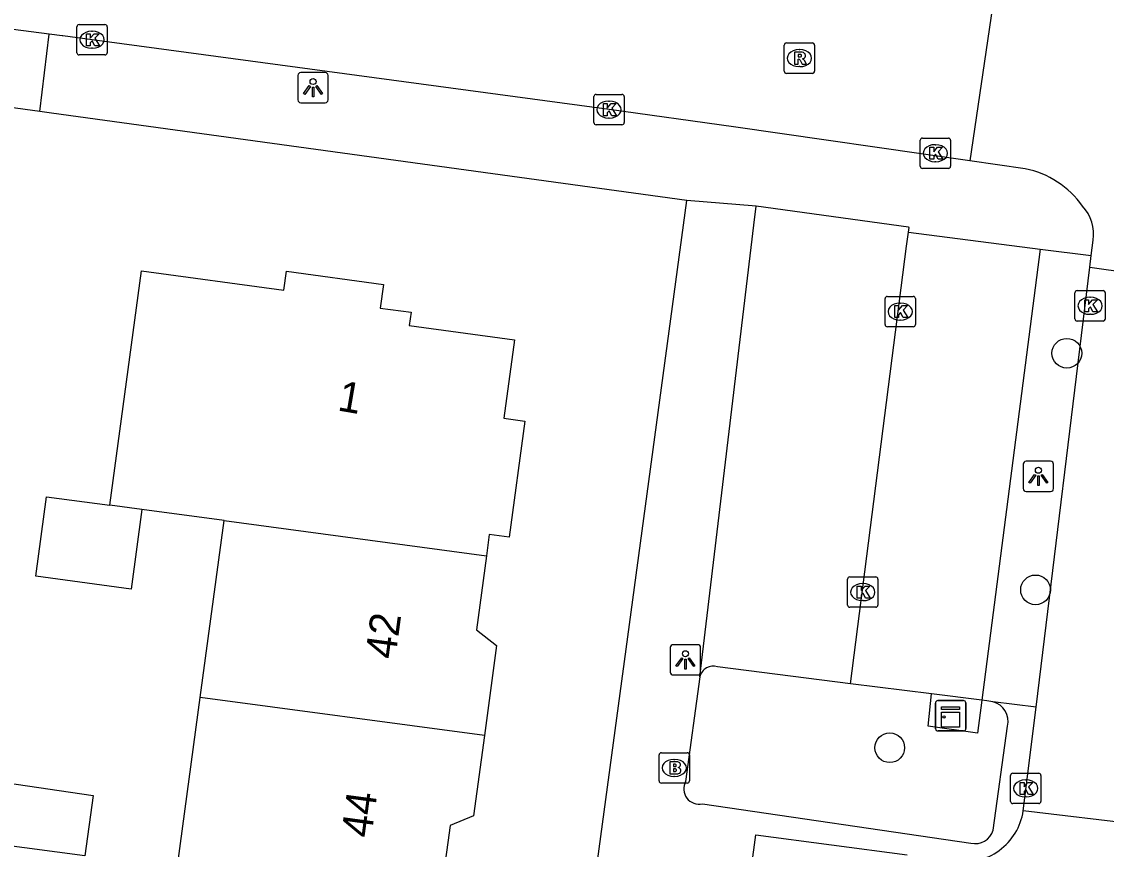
# Model space of a CAD drawing. Extents: x 161258 to 161838, y 380836 to 381727.
# Drawn here: x 161703.9 to 161739.61, y 381549.82 to 381577.07 of the extents above; entities that cross this region are included whole.
import ezdxf

# ---------------------------------------------------------------- set-up
doc = ezdxf.new("R2010")
doc.units = 0
for name, color, linetype in [('IMGEO_Boom', 7, 'Continuous'), ('IMGEO_Brandkraan', 7, 'Continuous'), ('IMGEO_Kast', 7, 'Continuous'), ('IMGEO_Kolk', 7, 'Continuous'), ('IMGEO_Lichtpunt', 7, 'Continuous'), ('IMGEO_Pand', 7, 'Continuous'), ('IMGEO_Pand_nummerreeks', 7, 'Continuous'), ('IMGEO_Parkeervlak_open', 7, 'Continuous'), ('IMGEO_Rijbaan_lokaal_open', 7, 'Continuous'), ('IMGEO_Rioolput', 7, 'Continuous'), ('IMGEO_Voetpad_open', 7, 'Continuous')]:
    doc.layers.add(name, color=color, linetype=linetype)

msp = doc.modelspace()

# ---------------------------------------------------------------- linework, layer by layer
at = {"layer": 'IMGEO_Boom'}
for centre in [(161738.307, 381566.149), (161737.276, 381558.359), (161732.475, 381553.163)]:
    msp.add_circle(centre, 0.489, dxfattribs=at)
at = {"layer": 'IMGEO_Brandkraan'}
for p, q in [((161724.958, 381552.998), (161725.81, 381552.998)), ((161724.883, 381552.072), (161724.883, 381552.924)), ((161725.371, 381552.778), (161725.396, 381552.778)), ((161725.884, 381552.924), (161725.884, 381552.072)), ((161725.81, 381551.998), (161724.958, 381551.998)), ((161725.394, 381552.218), (161725.369, 381552.218))]:
    msp.add_line(p, q, dxfattribs=at)
for points in [[(161724.958, 381552.998), (161725.81, 381552.998)], [(161724.883, 381552.072), (161724.883, 381552.924)], [(161725.231, 381552.698), (161725.231, 381552.298), (161725.444, 381552.298)], [(161725.462, 381552.698), (161725.231, 381552.698)], [(161725.41, 381552.617), (161725.356, 381552.617), (161725.356, 381552.541)], [(161725.884, 381552.924), (161725.884, 381552.072)], [(161725.356, 381552.541), (161725.409, 381552.541)], [(161725.418, 381552.465), (161725.356, 381552.465), (161725.356, 381552.384)], [(161725.356, 381552.384), (161725.418, 381552.384)], [(161725.81, 381551.998), (161724.958, 381551.998)]]:
    msp.add_lwpolyline(points, dxfattribs=at)
for centre, radius, start, end in [((161724.96, 381552.922), 0.0765, 91.552, 178.448), ((161724.96, 381552.922), 0.0765, 91.552, 178.448), ((161725.808, 381552.922), 0.0765, 1.552, 88.448), ((161725.808, 381552.922), 0.0765, 1.552, 88.448), ((161725.411, 381552.579), 0.0379, 267.8285, 90.9355), ((161725.466, 381552.553), 0.145, 59.4692, 91.5367), ((161725.491, 381552.6), 0.0922, 285.5137, 58.1501), ((161725.419, 381552.424), 0.0404, 269.8759, 90.5077), ((161725.45, 381552.549), 0.251, 268.6676, 293.5347), ((161725.496, 381552.408), 0.105, 301.3115, 78.989), ((161724.96, 381552.074), 0.0765, 181.552, 268.448), ((161724.96, 381552.074), 0.0765, 181.552, 268.448), ((161725.808, 381552.074), 0.0765, 271.552, 358.448), ((161725.808, 381552.074), 0.0765, 271.552, 358.448)]:
    msp.add_arc(centre, radius, start, end, dxfattribs=at)
for centre, major_axis, ratio, start_param, end_param in [((161725.37, 381552.498), (-0.387, 0.002), 0.722429, 4.712389, 7.853982), ((161725.395, 381552.498), (-0.39, 0.002), 0.717154, 1.570796, 4.712389)]:
    msp.add_ellipse(centre, major_axis=major_axis, ratio=ratio, start_param=start_param, end_param=end_param, dxfattribs=at)
at = {"layer": 'IMGEO_Kast'}
for p, q in [((161733.983, 381553.788), (161733.983, 381554.629)), ((161733.983, 381554.629), (161733.983, 381553.788)), ((161734.058, 381554.713), (161734.899, 381554.713)), ((161734.899, 381554.713), (161734.058, 381554.713)), ((161734.983, 381554.638), (161734.983, 381553.797)), ((161734.983, 381553.797), (161734.983, 381554.638)), ((161734.908, 381553.713), (161734.067, 381553.713)), ((161734.067, 381553.713), (161734.908, 381553.713))]:
    msp.add_line(p, q, dxfattribs=at)
for points in [[(161734.178, 381554.503), (161734.778, 381554.503), (161734.778, 381554.418), (161734.178, 381554.418), (161734.178, 381554.503)], [(161734.178, 381554.328), (161734.778, 381554.328), (161734.778, 381553.839), (161734.178, 381553.839), (161734.178, 381554.328)]]:
    msp.add_lwpolyline(points, dxfattribs=at)
msp.add_circle((161734.262, 381554.177), 0.0377, dxfattribs=at)
for centre, start, end in [((161734.061, 381554.635), 92.4484, 184.2845), ((161734.061, 381554.635), 92.4484, 184.2845), ((161734.905, 381554.635), 2.4484, 94.2845), ((161734.905, 381554.635), 2.4484, 94.2845), ((161734.061, 381553.791), 182.4484, 274.2845), ((161734.061, 381553.791), 182.4484, 274.2845), ((161734.905, 381553.791), 272.4484, 4.2845), ((161734.905, 381553.791), 272.4484, 4.2845)]:
    msp.add_arc(centre, 0.0779, start, end, dxfattribs=at)
at = {"layer": 'IMGEO_Kolk'}
for p, q in [((161705.713, 381576.047), (161705.713, 381576.899)), ((161705.788, 381576.973), (161706.64, 381576.973)), ((161706.714, 381576.899), (161706.714, 381576.047)), ((161706.201, 381576.753), (161706.226, 381576.753)), ((161706.224, 381576.193), (161706.199, 381576.193)), ((161706.64, 381575.973), (161705.788, 381575.973)), ((161722.733, 381573.747), (161722.733, 381574.599)), ((161722.808, 381574.673), (161723.66, 381574.673)), ((161723.221, 381574.453), (161723.246, 381574.453)), ((161723.734, 381574.599), (161723.734, 381573.747)), ((161723.66, 381573.673), (161722.808, 381573.673)), ((161723.244, 381573.893), (161723.219, 381573.893)), ((161733.48, 381572.311), (161733.48, 381573.163)), ((161733.555, 381573.237), (161734.407, 381573.237)), ((161733.968, 381573.017), (161733.993, 381573.017)), ((161734.481, 381573.163), (161734.481, 381572.311)), ((161734.407, 381572.237), (161733.555, 381572.237)), ((161733.991, 381572.457), (161733.966, 381572.457)), ((161732.322, 381567.097), (161732.322, 381567.949)), ((161732.397, 381568.023), (161733.249, 381568.023)), ((161733.323, 381567.949), (161733.323, 381567.097)), ((161738.573, 381567.286), (161738.573, 381568.138)), ((161738.648, 381568.212), (161739.5, 381568.212)), ((161739.061, 381567.992), (161739.086, 381567.992)), ((161739.574, 381568.138), (161739.574, 381567.286)), ((161732.81, 381567.803), (161732.835, 381567.803)), ((161732.833, 381567.243), (161732.808, 381567.243)), ((161739.084, 381567.432), (161739.059, 381567.432)), ((161733.249, 381567.023), (161732.397, 381567.023)), ((161739.5, 381567.212), (161738.648, 381567.212)), ((161731.088, 381557.859), (161731.088, 381558.711)), ((161731.163, 381558.785), (161732.015, 381558.785)), ((161732.089, 381558.711), (161732.089, 381557.859)), ((161731.576, 381558.565), (161731.601, 381558.565)), ((161731.599, 381558.005), (161731.574, 381558.005)), ((161732.015, 381557.785), (161731.163, 381557.785)), ((161736.453, 381551.396), (161736.453, 381552.248)), ((161736.528, 381552.322), (161737.38, 381552.322)), ((161737.454, 381552.248), (161737.454, 381551.396)), ((161736.941, 381552.102), (161736.966, 381552.102)), ((161736.964, 381551.542), (161736.939, 381551.542)), ((161737.38, 381551.322), (161736.528, 381551.322))]:
    msp.add_line(p, q, dxfattribs=at)
for points in [[(161705.713, 381576.047), (161705.713, 381576.899)], [(161705.788, 381576.973), (161706.64, 381576.973)], [(161706.714, 381576.899), (161706.714, 381576.047)], [(161706.034, 381576.673), (161706.157, 381576.673), (161706.157, 381576.522), (161706.287, 381576.673), (161706.451, 381576.673), (161706.305, 381576.522), (161706.458, 381576.273), (161706.306, 381576.273), (161706.221, 381576.437), (161706.157, 381576.37), (161706.157, 381576.273), (161706.034, 381576.273), (161706.034, 381576.673)], [(161706.64, 381575.973), (161705.788, 381575.973)], [(161722.733, 381573.747), (161722.733, 381574.599)], [(161722.808, 381574.673), (161723.66, 381574.673)], [(161723.054, 381574.373), (161723.177, 381574.373), (161723.177, 381574.222), (161723.307, 381574.373), (161723.471, 381574.373), (161723.325, 381574.222), (161723.478, 381573.973), (161723.326, 381573.973), (161723.241, 381574.137), (161723.177, 381574.07), (161723.177, 381573.973), (161723.054, 381573.973), (161723.054, 381574.373)], [(161723.734, 381574.599), (161723.734, 381573.747)], [(161723.66, 381573.673), (161722.808, 381573.673)], [(161733.48, 381572.311), (161733.48, 381573.163)], [(161733.555, 381573.237), (161734.407, 381573.237)], [(161733.801, 381572.937), (161733.924, 381572.937), (161733.924, 381572.786), (161734.054, 381572.937), (161734.218, 381572.937), (161734.072, 381572.786), (161734.225, 381572.537), (161734.073, 381572.537), (161733.988, 381572.701), (161733.924, 381572.634), (161733.924, 381572.537), (161733.801, 381572.537), (161733.801, 381572.937)], [(161734.481, 381573.163), (161734.481, 381572.311)], [(161734.407, 381572.237), (161733.555, 381572.237)], [(161732.322, 381567.097), (161732.322, 381567.949)], [(161732.397, 381568.023), (161733.249, 381568.023)], [(161733.323, 381567.949), (161733.323, 381567.097)], [(161738.573, 381567.286), (161738.573, 381568.138)], [(161738.648, 381568.212), (161739.5, 381568.212)], [(161739.574, 381568.138), (161739.574, 381567.286)], [(161732.643, 381567.723), (161732.766, 381567.723), (161732.766, 381567.572), (161732.896, 381567.723), (161733.06, 381567.723), (161732.914, 381567.572), (161733.067, 381567.323), (161732.915, 381567.323), (161732.83, 381567.487), (161732.766, 381567.42), (161732.766, 381567.323), (161732.643, 381567.323), (161732.643, 381567.723)], [(161738.894, 381567.912), (161739.017, 381567.912), (161739.017, 381567.761), (161739.147, 381567.912), (161739.311, 381567.912), (161739.165, 381567.761), (161739.318, 381567.512), (161739.166, 381567.512), (161739.081, 381567.676), (161739.017, 381567.609), (161739.017, 381567.512), (161738.894, 381567.512), (161738.894, 381567.912)], [(161733.249, 381567.023), (161732.397, 381567.023)], [(161739.5, 381567.212), (161738.648, 381567.212)], [(161731.088, 381557.859), (161731.088, 381558.711)], [(161731.163, 381558.785), (161732.015, 381558.785)], [(161732.089, 381558.711), (161732.089, 381557.859)], [(161731.409, 381558.485), (161731.532, 381558.485), (161731.532, 381558.334), (161731.662, 381558.485), (161731.826, 381558.485), (161731.68, 381558.334), (161731.833, 381558.085), (161731.681, 381558.085), (161731.596, 381558.249), (161731.532, 381558.182), (161731.532, 381558.085), (161731.409, 381558.085), (161731.409, 381558.485)], [(161732.015, 381557.785), (161731.163, 381557.785)], [(161736.453, 381551.396), (161736.453, 381552.248)], [(161736.528, 381552.322), (161737.38, 381552.322)], [(161737.454, 381552.248), (161737.454, 381551.396)], [(161736.774, 381552.022), (161736.897, 381552.022), (161736.897, 381551.871), (161737.027, 381552.022), (161737.191, 381552.022), (161737.045, 381551.871), (161737.198, 381551.622), (161737.046, 381551.622), (161736.961, 381551.786), (161736.897, 381551.719), (161736.897, 381551.622), (161736.774, 381551.622), (161736.774, 381552.022)], [(161737.38, 381551.322), (161736.528, 381551.322)]]:
    msp.add_lwpolyline(points, dxfattribs=at)
for centre, start, end in [((161705.79, 381576.897), 91.552, 178.448), ((161705.79, 381576.897), 91.552, 178.448), ((161706.638, 381576.897), 1.552, 88.448), ((161706.638, 381576.897), 1.552, 88.448), ((161705.79, 381576.049), 181.552, 268.448), ((161705.79, 381576.049), 181.552, 268.448), ((161706.638, 381576.049), 271.552, 358.448), ((161706.638, 381576.049), 271.552, 358.448), ((161722.81, 381574.597), 91.552, 178.448), ((161722.81, 381574.597), 91.552, 178.448), ((161723.658, 381574.597), 1.552, 88.448), ((161723.658, 381574.597), 1.552, 88.448), ((161722.81, 381573.749), 181.552, 268.448), ((161722.81, 381573.749), 181.552, 268.448), ((161723.658, 381573.749), 271.552, 358.448), ((161723.658, 381573.749), 271.552, 358.448), ((161733.557, 381573.161), 91.552, 178.448), ((161733.557, 381573.161), 91.552, 178.448), ((161734.405, 381573.161), 1.552, 88.448), ((161734.405, 381573.161), 1.552, 88.448), ((161733.557, 381572.313), 181.552, 268.448), ((161733.557, 381572.313), 181.552, 268.448), ((161734.405, 381572.313), 271.552, 358.448), ((161734.405, 381572.313), 271.552, 358.448), ((161732.399, 381567.947), 91.552, 178.448), ((161732.399, 381567.947), 91.552, 178.448), ((161733.247, 381567.947), 1.552, 88.448), ((161733.247, 381567.947), 1.552, 88.448), ((161738.65, 381568.136), 91.552, 178.448), ((161738.65, 381568.136), 91.552, 178.448), ((161739.498, 381568.136), 1.552, 88.448), ((161739.498, 381568.136), 1.552, 88.448), ((161738.65, 381567.288), 181.552, 268.448), ((161738.65, 381567.288), 181.552, 268.448), ((161739.498, 381567.288), 271.552, 358.448), ((161739.498, 381567.288), 271.552, 358.448), ((161732.399, 381567.099), 181.552, 268.448), ((161732.399, 381567.099), 181.552, 268.448), ((161733.247, 381567.099), 271.552, 358.448), ((161733.247, 381567.099), 271.552, 358.448), ((161731.165, 381558.709), 91.552, 178.448), ((161731.165, 381558.709), 91.552, 178.448), ((161732.013, 381558.709), 1.552, 88.448), ((161732.013, 381558.709), 1.552, 88.448), ((161731.165, 381557.861), 181.552, 268.448), ((161731.165, 381557.861), 181.552, 268.448), ((161732.013, 381557.861), 271.552, 358.448), ((161732.013, 381557.861), 271.552, 358.448), ((161736.53, 381552.246), 91.552, 178.448), ((161736.53, 381552.246), 91.552, 178.448), ((161737.378, 381552.246), 1.552, 88.448), ((161737.378, 381552.246), 1.552, 88.448), ((161736.53, 381551.398), 181.552, 268.448), ((161736.53, 381551.398), 181.552, 268.448), ((161737.378, 381551.398), 271.552, 358.448), ((161737.378, 381551.398), 271.552, 358.448)]:
    msp.add_arc(centre, 0.0765, start, end, dxfattribs=at)
for centre, major_axis, ratio, start_param, end_param in [((161706.2, 381576.473), (-0.387, 0.002), 0.722429, 4.712389, 7.853982), ((161706.225, 381576.473), (-0.39, 0.002), 0.717154, 1.570796, 4.712389), ((161723.22, 381574.173), (-0.387, 0.002), 0.722429, 4.712389, 7.853982), ((161723.245, 381574.173), (-0.39, 0.002), 0.717154, 1.570796, 4.712389), ((161733.967, 381572.737), (-0.387, 0.002), 0.722429, 4.712389, 7.853982), ((161733.992, 381572.737), (-0.39, 0.002), 0.717154, 1.570796, 4.712389), ((161739.06, 381567.712), (-0.387, 0.002), 0.722429, 4.712389, 7.853982), ((161739.085, 381567.712), (-0.39, 0.002), 0.717154, 1.570796, 4.712389), ((161732.809, 381567.523), (-0.387, 0.002), 0.722429, 4.712389, 7.853982), ((161732.834, 381567.523), (-0.39, 0.002), 0.717154, 1.570796, 4.712389), ((161731.575, 381558.285), (-0.387, 0.002), 0.722429, 4.712389, 7.853982), ((161731.6, 381558.285), (-0.39, 0.002), 0.717154, 1.570796, 4.712389), ((161736.94, 381551.822), (-0.387, 0.002), 0.722429, 4.712389, 7.853982), ((161736.965, 381551.822), (-0.39, 0.002), 0.717154, 1.570796, 4.712389)]:
    msp.add_ellipse(centre, major_axis=major_axis, ratio=ratio, start_param=start_param, end_param=end_param, dxfattribs=at)
at = {"layer": 'IMGEO_Lichtpunt'}
for p, q in [((161712.991, 381575.299), (161712.991, 381574.492)), ((161712.991, 381575.299), (161712.991, 381574.492)), ((161713.893, 381575.394), (161713.085, 381575.394)), ((161713.893, 381575.394), (161713.085, 381575.394)), ((161713.987, 381574.492), (161713.987, 381575.299)), ((161713.987, 381574.492), (161713.987, 381575.299)), ((161713.085, 381574.398), (161713.893, 381574.398)), ((161713.085, 381574.398), (161713.893, 381574.398)), ((161737.774, 381562.594), (161736.966, 381562.594)), ((161737.774, 381562.594), (161736.966, 381562.594)), ((161736.872, 381562.499), (161736.872, 381561.692)), ((161736.872, 381562.499), (161736.872, 381561.692)), ((161737.868, 381561.692), (161737.868, 381562.499)), ((161737.868, 381561.692), (161737.868, 381562.499)), ((161736.966, 381561.598), (161737.774, 381561.598)), ((161736.966, 381561.598), (161737.774, 381561.598)), ((161726.154, 381556.554), (161725.346, 381556.554)), ((161726.154, 381556.554), (161725.346, 381556.554)), ((161725.252, 381556.459), (161725.252, 381555.652)), ((161725.252, 381556.459), (161725.252, 381555.652)), ((161726.248, 381555.652), (161726.248, 381556.459)), ((161726.248, 381555.652), (161726.248, 381556.459)), ((161725.346, 381555.558), (161726.154, 381555.558)), ((161725.346, 381555.558), (161726.154, 381555.558))]:
    msp.add_line(p, q, dxfattribs=at)
for points in [[(161713.365, 381574.963), (161713.404, 381574.935), (161713.216, 381574.673), (161713.178, 381574.7), (161713.365, 381574.963)], [(161713.467, 381574.915), (161713.514, 381574.915), (161713.514, 381574.593), (161713.467, 381574.593), (161713.467, 381574.915)], [(161713.577, 381574.935), (161713.615, 381574.962), (161713.802, 381574.7), (161713.763, 381574.672), (161713.577, 381574.935)], [(161737.246, 381562.163), (161737.285, 381562.135), (161737.097, 381561.873), (161737.059, 381561.9), (161737.246, 381562.163)], [(161737.348, 381562.115), (161737.395, 381562.115), (161737.395, 381561.793), (161737.348, 381561.793), (161737.348, 381562.115)], [(161737.458, 381562.135), (161737.496, 381562.162), (161737.683, 381561.9), (161737.644, 381561.872), (161737.458, 381562.135)], [(161725.626, 381556.123), (161725.665, 381556.095), (161725.477, 381555.833), (161725.439, 381555.86), (161725.626, 381556.123)], [(161725.728, 381556.075), (161725.775, 381556.075), (161725.775, 381555.753), (161725.728, 381555.753), (161725.728, 381556.075)], [(161725.838, 381556.095), (161725.876, 381556.122), (161726.063, 381555.86), (161726.024, 381555.832), (161725.838, 381556.095)]]:
    msp.add_lwpolyline(points, dxfattribs=at)
for centre in [(161713.49, 381575.097), (161737.371, 381562.297), (161725.751, 381556.257)]:
    msp.add_circle(centre, 0.0994, dxfattribs=at)
for centre, start, end in [((161713.085, 381575.299), 90, 180), ((161713.085, 381575.299), 90, 180), ((161713.893, 381575.299), 0, 90), ((161713.893, 381575.299), 0, 90), ((161713.085, 381574.492), 180, 270), ((161713.085, 381574.492), 180, 270), ((161713.893, 381574.492), 270, 0), ((161713.893, 381574.492), 270, 360), ((161736.966, 381562.499), 90, 180), ((161736.966, 381562.499), 90, 180), ((161737.774, 381562.499), 0, 90), ((161737.774, 381562.499), 0, 90), ((161736.966, 381561.692), 180, 270), ((161736.966, 381561.692), 180, 270), ((161737.774, 381561.692), 270, 0), ((161737.774, 381561.692), 270, 360), ((161725.346, 381556.459), 90, 180), ((161725.346, 381556.459), 90, 180), ((161726.154, 381556.459), 0, 90), ((161726.154, 381556.459), 0, 90), ((161725.346, 381555.652), 180, 270), ((161725.346, 381555.652), 180, 270), ((161726.154, 381555.652), 270, 0), ((161726.154, 381555.652), 270, 360)]:
    msp.add_arc(centre, 0.0946, start, end, dxfattribs=at)
at = {"layer": 'IMGEO_Pand'}
for points in [[(161706.802, 381561.144), (161707.845, 381568.865), (161712.529, 381568.232), (161712.613, 381568.851), (161715.81, 381568.419), (161715.704, 381567.639), (161716.715, 381567.502), (161716.655, 381567.061), (161720.125, 381566.592), (161719.776, 381564.008), (161720.459, 381563.916), (161719.942, 381560.092), (161719.292, 381560.18), (161719.198, 381559.484)], [(161707.857, 381561.003), (161707.506, 381558.386), (161704.359, 381558.807), (161704.71, 381561.425), (161706.802, 381561.144)], [(161707.857, 381561.003), (161706.802, 381561.144)], [(161710.56, 381560.641), (161707.857, 381561.003)], [(161709.773, 381554.819), (161710.56, 381560.641)], [(161710.56, 381560.641), (161719.198, 381559.484)], [(161719.198, 381559.484), (161718.867, 381557.042), (161719.533, 381556.528), (161719.133, 381553.564)], [(161709.045, 381549.435), (161709.773, 381554.819)], [(161719.133, 381553.564), (161709.773, 381554.819)], [(161719.133, 381553.564), (161718.775, 381550.918), (161718.003, 381550.602), (161717.689, 381548.283)], [(161703.07, 381549.987), (161703.344, 381552.016), (161706.247, 381551.591), (161705.978, 381549.6), (161703.07, 381549.987)]]:
    msp.add_lwpolyline(points, dxfattribs=at)
at = {"layer": 'IMGEO_Parkeervlak_open'}
msp.add_lwpolyline([(161733.852, 381554.936), (161731.185, 381555.271)], dxfattribs=at)
at = {"layer": 'IMGEO_Rijbaan_lokaal_open'}
for points in [[(161704.805, 381576.659), (161697.936, 381577.548)], [(161735.86, 381577.557), (161735.113, 381572.49)], [(161735.113, 381572.49), (161727.337, 381573.606), (161723.234, 381574.173), (161706.214, 381576.473), (161705.253, 381576.601), (161705.23, 381576.604), (161704.805, 381576.659)], [(161736.937, 381572.228), (161735.113, 381572.49)], [(161726.222, 381555.497), (161727.999, 381570.369), (161728.08, 381570.99)], [(161733.096, 381570.138), (161733.118, 381570.296), (161733.091, 381570.3), (161728.08, 381570.99)], [(161731.185, 381555.271), (161733.033, 381569.676), (161733.096, 381570.138)], [(161739.108, 381569.367), (161739.17, 381569.87)], [(161739.062, 381568.989), (161739.108, 381569.367)], [(161737.298, 381554.499), (161739.062, 381568.989)], [(161739.062, 381568.989), (161743.094, 381568.418)], [(161731.185, 381555.271), (161726.803, 381555.821)], [(161736.87, 381551.083), (161737.298, 381554.499)], [(161740.738, 381550.621), (161736.87, 381551.083)]]:
    msp.add_lwpolyline(points, dxfattribs=at)
for centre, radius, start, end in [((161736.31, 381569.204), 3.088, 35.3948, 78.2808), ((161737.821, 381570.072), 1.364, 351.4809, 42.4878), ((161726.659, 381555.397), 0.448, 71.1794, 167.1138), ((161734.918, 381551.373), 1.973, 260.8004, 351.5604)]:
    msp.add_arc(centre, radius, start, end, dxfattribs=at)
at = {"layer": 'IMGEO_Rioolput'}
for p, q in [((161729.003, 381575.441), (161729.003, 381576.293)), ((161729.078, 381576.367), (161729.93, 381576.367)), ((161730.004, 381576.293), (161730.004, 381575.441)), ((161729.491, 381576.147), (161729.516, 381576.147)), ((161729.514, 381575.587), (161729.489, 381575.587)), ((161729.93, 381575.367), (161729.078, 381575.367))]:
    msp.add_line(p, q, dxfattribs=at)
for points in [[(161729.003, 381575.441), (161729.003, 381576.293)], [(161729.078, 381576.367), (161729.93, 381576.367)], [(161730.004, 381576.293), (161730.004, 381575.441)], [(161729.592, 381576.065), (161729.34, 381576.067), (161729.34, 381575.667)], [(161729.34, 381575.667), (161729.464, 381575.667), (161729.464, 381575.829), (161729.475, 381575.829)], [(161729.518, 381575.986), (161729.464, 381575.986), (161729.464, 381575.905)], [(161729.464, 381575.905), (161729.516, 381575.905)], [(161729.522, 381575.8), (161729.593, 381575.667), (161729.733, 381575.667), (161729.668, 381575.793)], [(161729.93, 381575.367), (161729.078, 381575.367)]]:
    msp.add_lwpolyline(points, dxfattribs=at)
for centre, radius, start, end in [((161729.08, 381576.291), 0.0765, 91.552, 178.448), ((161729.08, 381576.291), 0.0765, 91.552, 178.448), ((161729.928, 381576.291), 0.0765, 1.552, 88.448), ((161729.928, 381576.291), 0.0765, 1.552, 88.448), ((161729.474, 381575.776), 0.0533, 26.0293, 88.6989), ((161729.5, 381576.094), 0.19, 274.7715, 282.9687), ((161729.524, 381575.89), 0.0964, 77.0061, 93.1865), ((161729.538, 381575.947), 0.0378, 276.6634, 79.6772), ((161729.591, 381575.955), 0.109, 350.3612, 89.416), ((161729.589, 381575.955), 0.112, 277.5842, 350.9817), ((161729.573, 381575.74), 0.108, 29.5134, 73.7905), ((161729.08, 381575.443), 0.0765, 181.552, 268.448), ((161729.08, 381575.443), 0.0765, 181.552, 268.448), ((161729.928, 381575.443), 0.0765, 271.552, 358.448), ((161729.928, 381575.443), 0.0765, 271.552, 358.448)]:
    msp.add_arc(centre, radius, start, end, dxfattribs=at)
for centre, major_axis, ratio, start_param, end_param in [((161729.49, 381575.867), (-0.387, 0.002), 0.722429, 4.712389, 7.853982), ((161729.515, 381575.867), (-0.39, 0.002), 0.717154, 1.570796, 4.712389)]:
    msp.add_ellipse(centre, major_axis=major_axis, ratio=ratio, start_param=start_param, end_param=end_param, dxfattribs=at)
at = {"layer": 'IMGEO_Voetpad_open'}
for points in [[(161704.491, 381574.105), (161704.805, 381576.659)], [(161704.491, 381574.105), (161701.111, 381574.569)], [(161725.791, 381571.18), (161704.879, 381574.052), (161704.491, 381574.105)], [(161717.412, 381509.172), (161725.791, 381571.18)], [(161728.08, 381570.99), (161725.791, 381571.18)], [(161733.096, 381570.138), (161737.43, 381569.576)], [(161737.43, 381569.576), (161735.505, 381554.729)], [(161737.43, 381569.576), (161739.108, 381569.367)], [(161726.222, 381555.497), (161725.757, 381552.052)], [(161735.505, 381554.729), (161735.361, 381553.644), (161733.739, 381553.869), (161733.852, 381554.936)], [(161735.505, 381554.729), (161733.852, 381554.936)], [(161735.868, 381554.678), (161735.678, 381554.707), (161735.505, 381554.729)], [(161737.298, 381554.499), (161735.868, 381554.678)], [(161735.879, 381550.446), (161736.354, 381553.87)], [(161726.312, 381551.318), (161735.148, 381550.02)], [(161727.76, 381548.004), (161728.067, 381550.294), (161733.053, 381549.631)]]:
    msp.add_lwpolyline(points, dxfattribs=at)
for centre, radius, start, end in [((161735.703, 381554.028), 0.67, 346.3352, 75.7174), ((161726.198, 381551.809), 0.504, 151.0929, 283.0952), ((161735.291, 381550.614), 0.611, 256.4327, 344.0314)]:
    msp.add_arc(centre, radius, start, end, dxfattribs=at)

# ---------------------------------------------------------------- texts
at = {"layer": 'IMGEO_Pand_nummerreeks'}
for s, rotation, p in [('1', 350.2311, (161714.265, 381564.273)), ('42', 82.3602, (161716.196, 381556.053)), ('44', 82.3602, (161715.406, 381550.169))]:
    msp.add_text(s, height=1, rotation=rotation, dxfattribs=at).set_placement(p)

doc.saveas('drawing.dxf')
